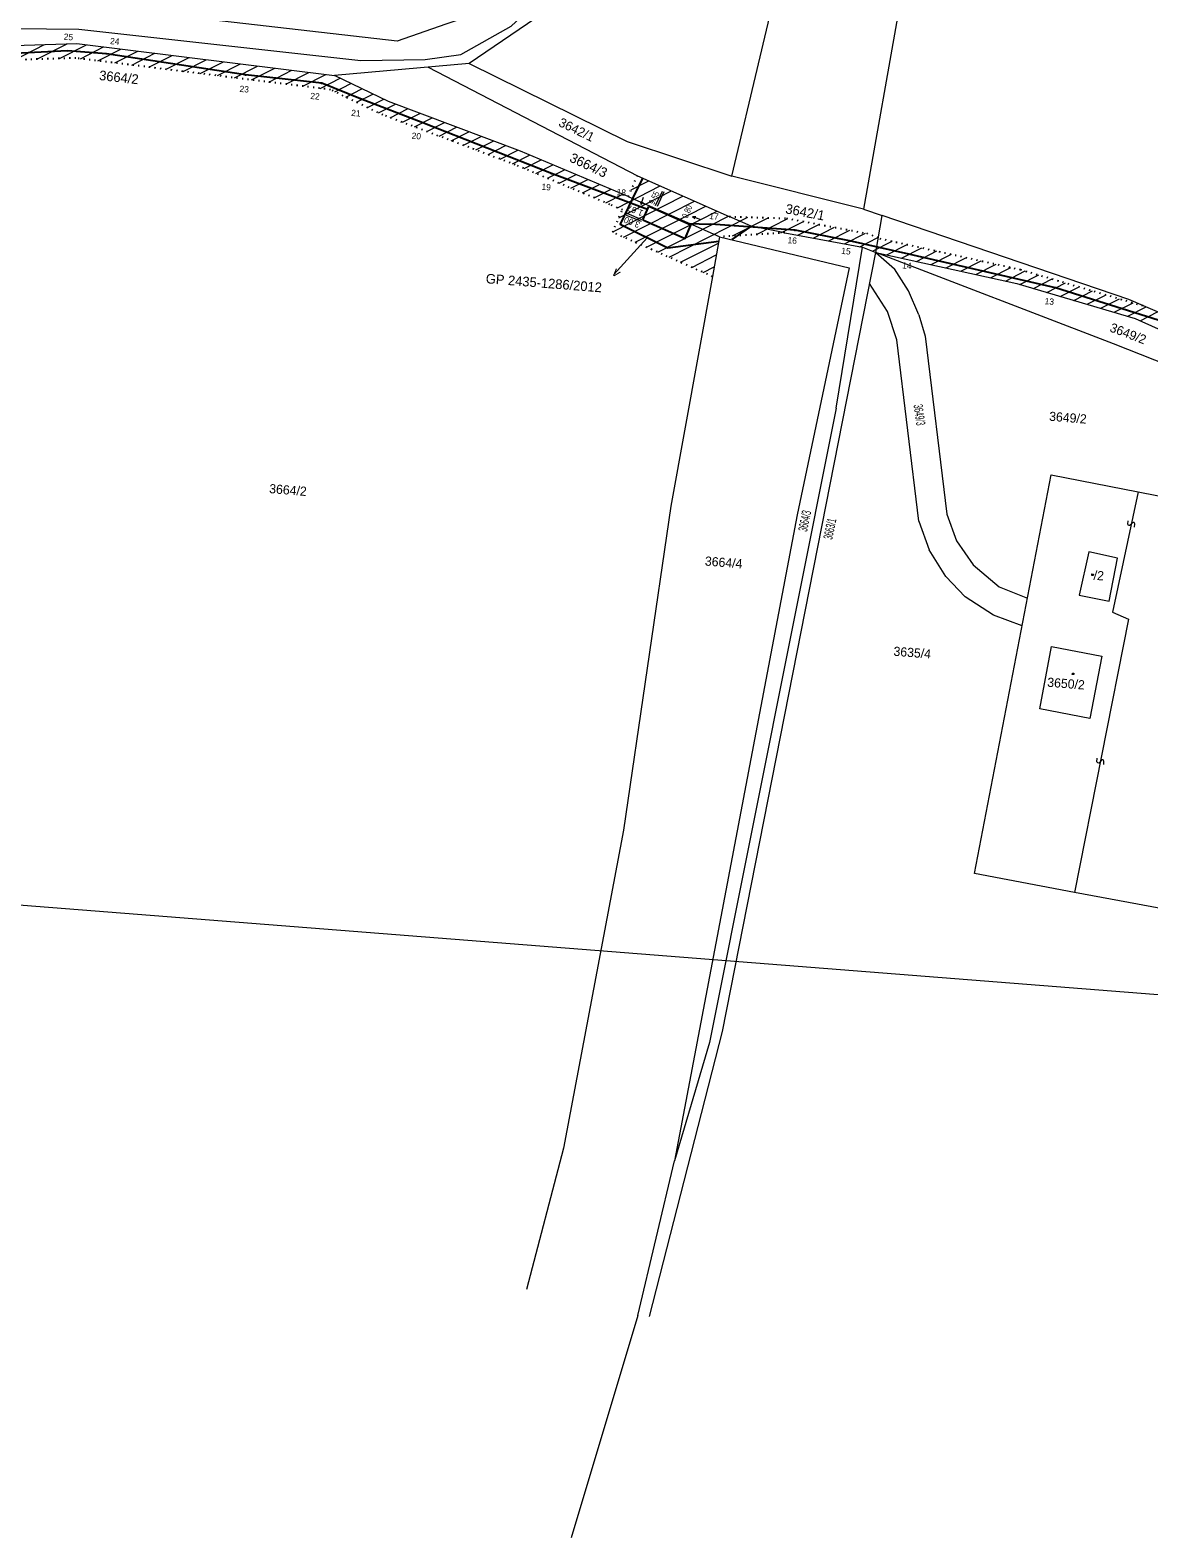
# Model space of a CAD drawing. Extents: x -686682 to -685519, y -959675 to -959188.
# Drawn here: x -685922.2 to -685690.5, y -959675.2 to -959362.9 of the extents above; entities that cross this region are included whole.
import ezdxf

# ---------------------------------------------------------------- set-up
doc = ezdxf.new("R2010")
doc.units = 0
doc.header["$LTSCALE"] = 0.76
doc.linetypes.add('DOTTED', pattern=[1.5, 0.3, -1.2])
for name, color, linetype, lineweight in [('1', 7, 'Continuous', 13), ('2', 7, 'Continuous', 25), ('3', 7, 'Continuous', 13)]:
    doc.layers.add(name, color=color, linetype=linetype, lineweight=lineweight)

msp = doc.modelspace()

# ---------------------------------------------------------------- linework, layer by layer
at = {"layer": '1', "linetype": 'DOTTED', "lineweight": 25}
for p, q in [((-685912.762, -959368.707), (-685943.077, -959369.638)), ((-685860.022, -959375.244), (-685912.762, -959368.707)), ((-685849.212, -959380.46), (-685860.019, -959375.246)), ((-685821.758, -959390.798), (-685849.212, -959380.46)), ((-685802.181, -959398.997), (-685821.758, -959390.798)), ((-685798.35, -959397.4), (-685796.46, -959393.08)), ((-685799.56, -959400.15), (-685802.181, -959398.997)), ((-685777.41, -959401.54), (-685765.581, -959401.875)), ((-685765.581, -959401.875), (-685748.978, -959405.002)), ((-685765.901, -959404.867), (-685779.43, -959405.7)), ((-685748.978, -959405.002), (-685746.23, -959406.06)), ((-685746.23, -959406.06), (-685717.13, -959412.49)), ((-685717.13, -959412.49), (-685691.616, -959420.013))]:
    msp.add_line(p, q, dxfattribs=at)
at = {"layer": '1'}
for p, q in [((-685798.35, -959397.4), (-685801, -959396.24)), ((-685792.67, -959399.259), (-685791.236, -959396.261)), ((-685792.303, -959399.383), (-685790.881, -959396.358)), ((-685795.664, -959399.041), (-685795.715, -959398.381)), ((-685795.664, -959399.041), (-685795.167, -959397.51)), ((-685795.664, -959399.041), (-685795.233, -959398.538)), ((-685798.744, -959401.205), (-685795.655, -959402.483)), ((-685798.637, -959400.832), (-685795.575, -959402.123)), ((-685785.015, -959401.501), (-685784.354, -959401.481)), ((-685785.015, -959401.501), (-685783.51, -959402.07)), ((-685785.015, -959401.501), (-685784.533, -959401.956)), ((-685749.6, -959400), (-685745.74, -959401.31)), ((-685694.66, -959418.71), (-685745.74, -959401.31)), ((-685779.43, -959405.7), (-685780.915, -959413.926)), ((-685765.901, -959404.867), (-685749.8, -959407.9)), ((-685755.269, -959441.215), (-685749.8, -959407.9)), ((-685749.8, -959407.9), (-685747.09, -959408.94)), ((-685747.09, -959408.94), (-685743.219, -959412.338)), ((-685697.86, -959427.86), (-685747.09, -959408.94)), ((-685642.9, -959449.61), (-685697.86, -959427.86)), ((-685738.175, -959464.627), (-685735.982, -959470.548)), ((-685796.38, -959629.16), (-685788.79, -959597.14)), ((-685796.38, -959629.16), (-685810.2, -959675.22))]:
    msp.add_line(p, q, dxfattribs=at)
at = {"layer": '1', "lineweight": 25}
msp.add_line((-685795.32, -959402.22), (-685794.1, -959399.45), dxfattribs=at)
at = {"layer": '1'}
for points in [[(-686681.662, -959484.53), (-685585.053, -959570.835), (-685561.751, -959274.75), (-686658.36, -959188.445)], [(-685914.607, -959367.301), (-685914.591, -959367.102), (-685914.392, -959367.118), (-685914.408, -959367.317)], [(-685906.527, -959367.901), (-685906.511, -959367.702), (-685906.312, -959367.718), (-685906.328, -959367.917)], [(-685877.7, -959372.3), (-685877.7, -959372.1), (-685877.5, -959372.1), (-685877.5, -959372.3)], [(-685861.92, -959374.02), (-685861.92, -959373.82), (-685861.72, -959373.82), (-685861.72, -959374.02)], [(-685853.91, -959377.24), (-685853.91, -959377.04), (-685853.71, -959377.04), (-685853.71, -959377.24)], [(-685841.017, -959382.171), (-685841.001, -959381.972), (-685840.802, -959381.988), (-685840.818, -959382.187)], [(-685814.337, -959392.731), (-685814.321, -959392.532), (-685814.122, -959392.548), (-685814.138, -959392.747)], [(-685781.367, -959403.201), (-685781.351, -959403.002), (-685781.152, -959403.018), (-685781.168, -959403.217)], [(-685763.897, -959404.471), (-685763.881, -959404.272), (-685763.682, -959404.288), (-685763.698, -959404.487)], [(-685752.607, -959406.661), (-685752.591, -959406.462), (-685752.392, -959406.478), (-685752.408, -959406.677)], [(-685752.607, -959406.661), (-685752.591, -959406.462), (-685752.392, -959406.478), (-685752.408, -959406.677)], [(-685740.357, -959409.391), (-685740.341, -959409.192), (-685740.142, -959409.208), (-685740.158, -959409.407)], [(-685740.357, -959409.391), (-685740.341, -959409.192), (-685740.142, -959409.208), (-685740.158, -959409.407)], [(-685709.947, -959416.351), (-685709.931, -959416.152), (-685709.732, -959416.168), (-685709.748, -959416.367)], [(-685702.96, -959471), (-685704.93, -959479.98), (-685698.73, -959481.18), (-685697.02, -959472.29)], [(-685702.306, -959475.554), (-685702.007, -959475.578), (-685702.03, -959475.877), (-685702.33, -959475.853)], [(-685710.66, -959490.62), (-685700.27, -959492.62), (-685702.75, -959505.49), (-685713.12, -959503.5)], [(-685706.355, -959496.086), (-685706.056, -959496.11), (-685706.08, -959496.409), (-685706.379, -959496.385)]]:
    msp.add_lwpolyline(points, close=True, dxfattribs=at)
for points in [[(-686204.063, -959379.791), (-686066.016, -959368.791), (-685932.223, -959362.514), (-685912.138, -959362.723), (-685853.767, -959369.209), (-685840.377, -959369), (-685833.055, -959367.954), (-685822.594, -959362.096), (-685812.133, -959352.263), (-685781.902, -959299.854), (-685762.445, -959268.42), (-685671.271, -959203.792)], [(-685680.796, -959203.792), (-685713.942, -959227.414), (-685755.506, -959257.541), (-685766.106, -959266.188), (-685787.237, -959298.93), (-685808.263, -959337.775), (-685817.678, -959351.583), (-685823.954, -959357.65), (-685836.161, -959361.703), (-685846.235, -959365.182), (-685911.929, -959357.65), (-685930.968, -959357.859), (-686094.888, -959365.809), (-686195.703, -959372.289)], [(-685722.14, -959243.4), (-685754.66, -959265.62), (-685758.278, -959268.574), (-685808.836, -959354.509), (-685831.277, -959369.821), (-685859.16, -959372.33)], [(-685722.14, -959243.4), (-685730.28, -959269.26), (-685741.85, -959355.88), (-685749.6, -959400)], [(-685749.6, -959400), (-685776.9, -959393.16), (-685765.13, -959343.64), (-685762.47, -959322.7), (-685754.66, -959265.62)], [(-686023.54, -959370.88), (-685977.27, -959367.57), (-685943.16, -959366.64), (-685912.57, -959365.7), (-685859.16, -959372.33)], [(-685839.801, -959370.588), (-685796.46, -959393.08), (-685777.41, -959401.54)], [(-685831.277, -959369.821), (-685798.54, -959385.992), (-685776.9, -959393.16)], [(-685801, -959396.24), (-685820.65, -959388.01), (-685848.03, -959377.7), (-685859.16, -959372.33)], [(-685779.43, -959405.7), (-685752.57, -959412.16), (-685763.39, -959463.28), (-685788.79, -959597.14)], [(-685779.43, -959405.7), (-685752.57, -959412.16), (-685763.39, -959463.28), (-685788.79, -959597.14)], [(-685793.939, -959629.375), (-685778.857, -959570.336), (-685747.09, -959408.94)], [(-685747.09, -959408.94), (-685717.88, -959415.4), (-685693.35, -959422.63), (-685666.15, -959434.85)], [(-685780.915, -959413.926), (-685789.5, -959461.55), (-685799.34, -959528.64), (-685811.79, -959594.5), (-685819.418, -959623.782)], [(-685738.175, -959421.915), (-685740.295, -959416.944), (-685743.219, -959412.338)], [(-685738.175, -959464.627), (-685742.707, -959427.069), (-685744.681, -959421.184), (-685748.36, -959415.395)], [(-685664.52, -959431.62), (-685691.62, -959420.01), (-685694.66, -959418.71)], [(-685738.175, -959421.915), (-685736.859, -959426.301), (-685732.327, -959463.201), (-685730.353, -959468.684), (-685726.917, -959473.655), (-685721.507, -959478.224), (-685715.642, -959480.567)], [(-685755.269, -959441.215), (-685781.51, -959572.613), (-685788.79, -959597.14)], [(-685649.66, -959551.97), (-685705.88, -959541.57), (-685726.6, -959537.62), (-685710.74, -959455.04), (-685692.73, -959458.56), (-685646.23, -959467.67), (-685642.9, -959449.61)], [(-685692.73, -959458.56), (-685698.05, -959483.5), (-685694.73, -959484.94), (-685705.88, -959541.57)], [(-685693.471, -959465.873), (-685693.423, -959465.167), (-685693.577, -959464.93), (-685693.773, -959464.888), (-685694.01, -959465.042), (-685694.289, -959465.391), (-685694.526, -959465.545), (-685694.722, -959465.504), (-685694.876, -959465.266), (-685694.828, -959464.561)], [(-685716.739, -959486.28), (-685722.677, -959484.073), (-685728.525, -959480.271), (-685732.546, -959476.104), (-685735.982, -959470.548)], [(-685699.84, -959515.037), (-685699.803, -959514.331), (-685699.961, -959514.096), (-685700.157, -959514.058), (-685700.392, -959514.215), (-685700.665, -959514.569), (-685700.9, -959514.727), (-685701.096, -959514.688), (-685701.254, -959514.453), (-685701.217, -959513.747)]]:
    msp.add_lwpolyline(points, dxfattribs=at)
at = {"layer": '1', "linetype": 'DOTTED', "lineweight": 25}
msp.add_lwpolyline([(-685780.915, -959413.926), (-685801.59, -959404.78), (-685799.56, -959400.15)], dxfattribs=at)
at = {"layer": '2', "lineweight": 13}
for p, q in [((-685798.35, -959397.4), (-685795.148, -959398.806)), ((-685772.9, -959403.55), (-685777.41, -959401.54)), ((-685747.09, -959408.94), (-685745.74, -959401.31)), ((-685779.43, -959405.7), (-685784.924, -959403.29)), ((-685765.902, -959404.867), (-685772.9, -959403.55)), ((-685794.435, -959405.928), (-685801.305, -959413.562))]:
    msp.add_line(p, q, dxfattribs=at)
at = {"layer": '2'}
for p, q in [((-685786.08, -959402.96), (-685781.26, -959403.11)), ((-685772.9, -959403.55), (-685776.91, -959406.31))]:
    msp.add_line(p, q, dxfattribs=at)
for points in [[(-685794.369, -959400.062), (-685814.23, -959392.64), (-685840.91, -959382.08), (-685853.81, -959377.14), (-685861.82, -959373.92), (-685877.6, -959372.2), (-685906.42, -959367.81), (-685914.5, -959367.21), (-685943.17, -959368.62), (-685977.12, -959370.01), (-685999.85, -959370.76), (-686012.6, -959371.83), (-686033.98, -959372.46), (-686068.26, -959373.33), (-686093.73, -959375.88), (-686117.3, -959377.34), (-686123.803, -959377.419)], [(-685795.39, -959393.55), (-685797.44, -959397.8), (-685799.99, -959403.08), (-685790.17, -959408.01), (-685779.6, -959406.65)], [(-685795.32, -959402.22), (-685786.58, -959406.06), (-685785.35, -959403.28), (-685794.1, -959399.45)], [(-685677.639, -959427.688), (-685685.93, -959423.85), (-685709.84, -959416.26), (-685740.25, -959409.3), (-685752.5, -959406.57), (-685763.79, -959404.38), (-685781.26, -959403.11)]]:
    msp.add_lwpolyline(points, dxfattribs=at)
at = {"layer": '2', "lineweight": 13}
msp.add_lwpolyline([(-685784.924, -959403.29), (-685793.771, -959399.41), (-685795.148, -959398.806)], dxfattribs=at)
at = {"layer": '3'}
for p, q in [((-685925.537, -959369.099), (-685919.268, -959365.905)), ((-685920.849, -959368.955), (-685914.58, -959365.761)), ((-685916.161, -959368.811), (-685910.546, -959365.951)), ((-685911.787, -959368.828), (-685907.004, -959366.39)), ((-685908.244, -959369.267), (-685903.462, -959366.83)), ((-685904.701, -959369.706), (-685899.919, -959367.27)), ((-685901.157, -959370.145), (-685896.377, -959367.71)), ((-685897.614, -959370.585), (-685892.835, -959368.149)), ((-685894.071, -959371.024), (-685889.292, -959368.589)), ((-685890.527, -959371.463), (-685885.75, -959369.029)), ((-685886.984, -959371.902), (-685882.207, -959369.468)), ((-685883.441, -959372.341), (-685878.665, -959369.908)), ((-685879.897, -959372.781), (-685875.123, -959370.348)), ((-685876.354, -959373.22), (-685871.58, -959370.788)), ((-685872.811, -959373.659), (-685868.038, -959371.227)), ((-685869.267, -959374.098), (-685864.496, -959371.667)), ((-685865.724, -959374.538), (-685860.953, -959372.107)), ((-685862.181, -959374.977), (-685858.043, -959372.868)), ((-685859.138, -959375.671), (-685855.78, -959373.96)), ((-685856.875, -959376.763), (-685853.517, -959375.052)), ((-685854.612, -959377.854), (-685851.254, -959376.144)), ((-685852.349, -959378.946), (-685848.992, -959377.235)), ((-685850.087, -959380.038), (-685846.573, -959378.248)), ((-685847.658, -959381.045), (-685844.04, -959379.202)), ((-685845.125, -959381.999), (-685841.507, -959380.156)), ((-685842.591, -959382.953), (-685838.974, -959381.11)), ((-685840.058, -959383.907), (-685836.44, -959382.063)), ((-685837.525, -959384.861), (-685833.907, -959383.017)), ((-685834.992, -959385.815), (-685831.374, -959383.971)), ((-685832.458, -959386.768), (-685828.841, -959384.925)), ((-685829.925, -959387.722), (-685826.307, -959385.879)), ((-685827.392, -959388.676), (-685823.774, -959386.833)), ((-685824.859, -959389.63), (-685821.241, -959387.787)), ((-685822.325, -959390.584), (-685818.796, -959388.786)), ((-685819.882, -959391.584), (-685816.378, -959389.798)), ((-685817.464, -959392.596), (-685813.96, -959390.811)), ((-685815.046, -959393.609), (-685811.542, -959391.824)), ((-685812.628, -959394.622), (-685809.125, -959392.836)), ((-685810.21, -959395.634), (-685806.707, -959393.849)), ((-685807.792, -959396.647), (-685804.289, -959394.862)), ((-685805.374, -959397.66), (-685801.871, -959395.875)), ((-685800.575, -959399.703), (-685791.712, -959395.188)), ((-685800.283, -959401.799), (-685789.358, -959396.233)), ((-685797.745, -959396.017), (-685794.066, -959394.142)), ((-685802.957, -959398.672), (-685799.484, -959396.903)), ((-685801.55, -959404.69), (-685787.005, -959397.278)), ((-685799.305, -959405.79), (-685784.651, -959398.324)), ((-685796.947, -959406.834), (-685782.297, -959399.369)), ((-685794.589, -959407.877), (-685779.943, -959400.414)), ((-685792.231, -959408.92), (-685777.589, -959401.46)), ((-685789.873, -959409.963), (-685773.555, -959401.649)), ((-685776.78, -959405.537), (-685769.382, -959401.767)), ((-685771.77, -959405.228), (-685765.294, -959401.929)), ((-685766.76, -959404.92), (-685762.078, -959402.535)), ((-685763.236, -959405.369), (-685758.861, -959403.14)), ((-685760.019, -959405.975), (-685755.644, -959403.746)), ((-685756.802, -959406.581), (-685752.428, -959404.352)), ((-685753.586, -959407.186), (-685749.211, -959404.958)), ((-685787.515, -959411.006), (-685779.666, -959407.007)), ((-685750.369, -959407.792), (-685746.651, -959405.897)), ((-685747.732, -959408.693), (-685743.672, -959406.625)), ((-685744.803, -959409.445), (-685740.599, -959407.304)), ((-685741.731, -959410.125), (-685737.527, -959407.983)), ((-685738.659, -959410.804), (-685734.454, -959408.661)), ((-685785.157, -959412.05), (-685780.112, -959409.479)), ((-685782.799, -959413.093), (-685780.558, -959411.951)), ((-685735.587, -959411.483), (-685731.381, -959409.34)), ((-685732.515, -959412.163), (-685728.308, -959410.019)), ((-685729.443, -959412.842), (-685725.235, -959410.698)), ((-685726.371, -959413.522), (-685722.163, -959411.377)), ((-685723.299, -959414.201), (-685719.09, -959412.056)), ((-685720.227, -959414.88), (-685716.119, -959412.787)), ((-685717.221, -959415.594), (-685713.328, -959413.61)), ((-685714.43, -959416.416), (-685710.537, -959414.433)), ((-685711.639, -959417.239), (-685707.747, -959415.255)), ((-685708.848, -959418.061), (-685704.956, -959416.078)), ((-685706.057, -959418.884), (-685702.165, -959416.901)), ((-685703.266, -959419.707), (-685699.374, -959417.723)), ((-685700.476, -959420.529), (-685696.584, -959418.546)), ((-685697.685, -959421.352), (-685693.793, -959419.369)), ((-685694.894, -959422.174), (-685691.09, -959420.236)), ((-685692.304, -959423.099), (-685688.697, -959421.262))]:
    msp.add_line(p, q, dxfattribs=at)

# ---------------------------------------------------------------- texts
at = {"layer": '1'}
for s, height, rotation, p in [('25', 1.3, 355.5, (-685915.314, -959364.89)), ('24', 1.3, 355.5, (-685905.713, -959365.797)), ('3664/2', 2, 353.7, (-685908.02, -959373.231)), ('23', 1.3, 355.5, (-685878.897, -959375.705)), ('22', 1.3, 355.5, (-685864.24, -959377.171)), ('21', 1.3, 355.5, (-685855.765, -959380.676)), ('3642/1', 1.9, 333.9, (-685812.944, -959382.677)), ('20', 1.3, 355.5, (-685843.248, -959385.414)), ('3664/3', 2, 334.8, (-685810.685, -959390.051)), ('19', 1.3, 355.5, (-685816.354, -959395.988)), ('18', 1.3, 355.5, (-685800.796, -959397.085)), ('1,67', 1.3, 157.5, (-685795.106, -959400.337)), ('3642/1', 2, 349.2, (-685765.91, -959400.832)), ('3.00', 1.3, 158.4, (-685795.774, -959402.73)), ('17', 1.3, 355.5, (-685781.596, -959402.039)), ('16', 1.3, 355.5, (-685765.394, -959407.045)), ('15', 1.3, 355.5, (-685754.255, -959409.264)), ('14', 1.3, 355.5, (-685741.64, -959412.261)), ('GP 2435-1286/2012', 2, 355.5, (-685827.908, -959415.34)), ('v', 2, 319.5, (-685801.886, -959413.393)), ('13', 1.3, 355.5, (-685712.133, -959419.677)), ('3649/2', 1.9, 339.3, (-685698.775, -959425.275)), ('3649/2', 1.9, 355.5, (-685711.216, -959443.821)), ('3664/2', 1.9, 355.5, (-685872.769, -959458.808)), ('3664/4', 1.9, 355.5, (-685782.525, -959473.803)), ('/2', 1.9, 355.5, (-685702.007, -959476.752)), ('3635/4', 1.9, 355.5, (-685743.461, -959492.489)), ('3650/2', 1.9, 355.5, (-685711.611, -959498.906))]:
    msp.add_text(s, height=height, rotation=rotation, dxfattribs=at).set_placement(p)
for s, height, rotation, width, p in [('9.55', 1.3, 63.9, 0.65, (-685793.007, -959399.161)), ('0.80', 1.3, 67.5, 0.65, (-685786.086, -959402.001)), ('3649/3', 1.9, 278.1, 0.45, (-685739.266, -959440.568)), ('3664/3', 1.9, 78.3, 0.45, (-685761.318, -959466.907)), ('3663/1', 1.9, 78.3, 0.45, (-685756.103, -959468.554))]:
    msp.add_text(s, height=height, rotation=rotation, dxfattribs=dict(at, width=width)).set_placement(p)

doc.saveas('drawing.dxf')
